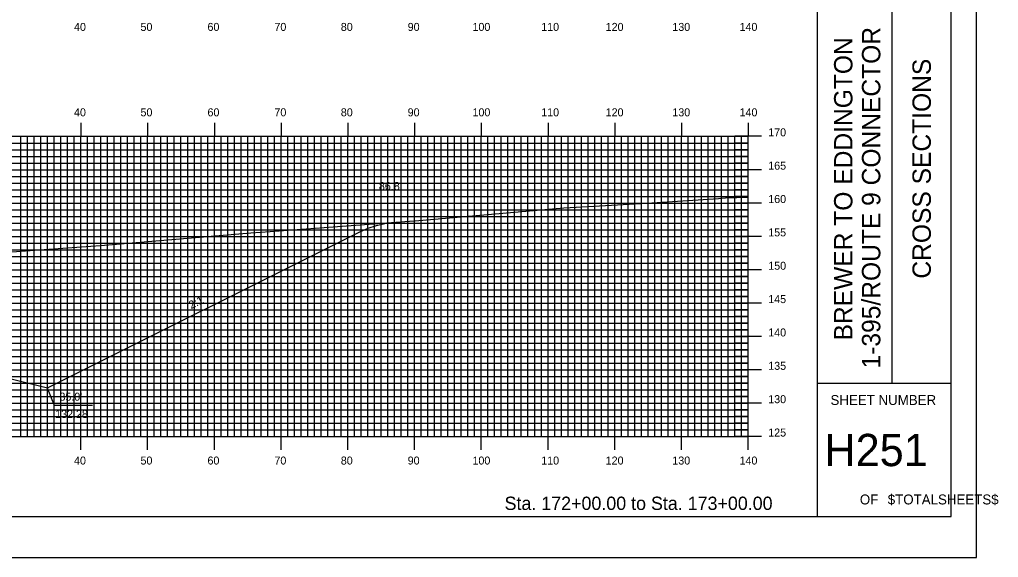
# Model space of a CAD drawing. Extents: x 1783041 to 1783384, y 442591 to 442811.
# Drawn here: x 1783237.3 to 1783384, y 442590.5 to 442671.2 of the extents above; entities that cross this region are included whole.
import ezdxf

# ---------------------------------------------------------------- set-up
doc = ezdxf.new("R2010")
doc.units = 0
for name, color, linetype in [('ANNOTATION', 7, 'Continuous'), ('BORDER', 7, 'Continuous'), ('D_Roadway_Centerline', 7, 'Continuous'), ('D_Roadway_SlopeLines', 7, 'Continuous'), ('D_Text_Standard', 7, 'Continuous'), ('H_V ANNOTATION', 7, 'Continuous'), ('MAJOR', 7, 'Continuous'), ('MINOR', 7, 'Continuous'), ('PLOT BOUNDARY', 7, 'Continuous'), ('S_Roadway_Centerline', 7, 'Continuous')]:
    doc.layers.add(name, color=color, linetype=linetype)

msp = doc.modelspace()

# ---------------------------------------------------------------- linework, layer by layer
at = {"layer": 'ANNOTATION'}
msp.add_lwpolyline([(1783248.2, 442613.32), (1783242.51, 442613.32), (1783241.4, 442616)], dxfattribs=at)
at = {"layer": 'BORDER'}
for p, q in [((1783356.86, 442596.67), (1783356.86, 442806.67)), ((1783368.04, 442616.67), (1783368.04, 442686.67)), ((1783368.04, 442616.67), (1783368.04, 442686.67)), ((1783356.86, 442616.67), (1783376.86, 442616.67)), ((1783356.86, 442616.67), (1783376.86, 442616.67))]:
    msp.add_line(p, q, dxfattribs=at)
msp.add_lwpolyline([(1783056.86, 442596.67), (1783376.86, 442596.67), (1783376.86, 442806.67), (1783056.86, 442806.67)], close=True, dxfattribs=at)
at = {"layer": 'D_Roadway_Centerline'}
msp.add_lwpolyline([(1783143.39, 442629.05), (1783144.64, 442629.1), (1783145.89, 442628.96), (1783147.14, 442628.63), (1783148.39, 442628.1), (1783172.29, 442616.15), (1783176.29, 442617.15), (1783186.46, 442619.69), (1783194.46, 442620.01), (1783206.46, 442620.25), (1783218.46, 442620.01), (1783226.46, 442619.69), (1783236.63, 442617.15), (1783241.45, 442615.95), (1783288.24, 442639.34), (1783289.49, 442639.9), (1783290.74, 442640.32), (1783291.99, 442640.61), (1783293.24, 442640.77)], dxfattribs=at)
at = {"layer": 'D_Roadway_SlopeLines'}
for points in [[(1783241.45, 442615.95), (1783288.24, 442639.34), (1783289.49, 442639.9), (1783290.74, 442640.32), (1783291.99, 442640.61), (1783293.24, 442640.77)], [(1783226.46, 442619.69), (1783241.45, 442615.95)]]:
    msp.add_lwpolyline(points, dxfattribs=at)
at = {"layer": 'MAJOR'}
for p, q in [((1783246.46, 442655.67), (1783246.46, 442653.67)), ((1783256.46, 442655.67), (1783256.46, 442653.67)), ((1783266.46, 442655.67), (1783266.46, 442653.67)), ((1783276.46, 442655.67), (1783276.46, 442653.67)), ((1783286.46, 442655.67), (1783286.46, 442653.67)), ((1783296.46, 442655.67), (1783296.46, 442653.67)), ((1783306.46, 442655.67), (1783306.46, 442653.67)), ((1783316.46, 442655.67), (1783316.46, 442653.67)), ((1783326.46, 442655.67), (1783326.46, 442653.67)), ((1783336.46, 442655.67), (1783336.46, 442653.67)), ((1783346.46, 442655.67), (1783346.46, 442653.67)), ((1783066.46, 442653.67), (1783346.46, 442653.67)), ((1783066.46, 442653.67), (1783346.46, 442653.67)), ((1783246.46, 442608.67), (1783246.46, 442653.67)), ((1783256.46, 442608.67), (1783256.46, 442653.67)), ((1783266.46, 442608.67), (1783266.46, 442653.67)), ((1783276.46, 442608.67), (1783276.46, 442653.67)), ((1783286.46, 442608.67), (1783286.46, 442653.67)), ((1783296.46, 442608.67), (1783296.46, 442653.67)), ((1783306.46, 442608.67), (1783306.46, 442653.67)), ((1783316.46, 442608.67), (1783316.46, 442653.67)), ((1783326.46, 442608.67), (1783326.46, 442653.67)), ((1783336.46, 442608.67), (1783336.46, 442653.67)), ((1783348.46, 442653.67), (1783344.46, 442653.67)), ((1783346.46, 442608.67), (1783346.46, 442653.67)), ((1783346.46, 442608.67), (1783346.46, 442653.67)), ((1783066.46, 442648.67), (1783346.46, 442648.67)), ((1783348.46, 442648.67), (1783344.46, 442648.67)), ((1783066.46, 442643.67), (1783346.46, 442643.67)), ((1783348.46, 442643.67), (1783344.46, 442643.67)), ((1783066.46, 442638.67), (1783346.46, 442638.67)), ((1783348.46, 442638.67), (1783344.46, 442638.67)), ((1783066.46, 442633.67), (1783346.46, 442633.67)), ((1783348.46, 442633.67), (1783344.46, 442633.67)), ((1783066.46, 442628.67), (1783346.46, 442628.67)), ((1783348.46, 442628.67), (1783344.46, 442628.67)), ((1783066.46, 442623.67), (1783346.46, 442623.67)), ((1783348.46, 442623.67), (1783344.46, 442623.67)), ((1783066.46, 442618.67), (1783346.46, 442618.67)), ((1783348.46, 442618.67), (1783344.46, 442618.67)), ((1783066.46, 442613.67), (1783346.46, 442613.67)), ((1783348.46, 442613.67), (1783344.46, 442613.67)), ((1783066.46, 442608.67), (1783346.46, 442608.67)), ((1783066.46, 442608.67), (1783346.46, 442608.67)), ((1783246.46, 442606.66), (1783246.46, 442608.67)), ((1783256.46, 442606.66), (1783256.46, 442608.67)), ((1783266.46, 442606.66), (1783266.46, 442608.67)), ((1783276.46, 442606.66), (1783276.46, 442608.67)), ((1783286.46, 442606.66), (1783286.46, 442608.67)), ((1783296.46, 442606.66), (1783296.46, 442608.67)), ((1783306.46, 442606.66), (1783306.46, 442608.67)), ((1783316.46, 442606.66), (1783316.46, 442608.67)), ((1783326.46, 442606.66), (1783326.46, 442608.67)), ((1783336.46, 442606.66), (1783336.46, 442608.67)), ((1783348.46, 442608.67), (1783344.46, 442608.67)), ((1783346.46, 442606.66), (1783346.46, 442608.67))]:
    msp.add_line(p, q, dxfattribs=at)
at = {"layer": 'MINOR'}
for p, q in [((1783066.46, 442652.67), (1783346.46, 442652.67)), ((1783237.46, 442608.67), (1783237.46, 442653.67)), ((1783238.46, 442608.67), (1783238.46, 442653.67)), ((1783239.46, 442608.67), (1783239.46, 442653.67)), ((1783240.46, 442608.67), (1783240.46, 442653.67)), ((1783241.46, 442608.67), (1783241.46, 442653.67)), ((1783242.46, 442608.67), (1783242.46, 442653.67)), ((1783243.46, 442608.67), (1783243.46, 442653.67)), ((1783244.46, 442608.67), (1783244.46, 442653.67)), ((1783245.46, 442608.67), (1783245.46, 442653.67)), ((1783247.46, 442608.67), (1783247.46, 442653.67)), ((1783248.46, 442608.67), (1783248.46, 442653.67)), ((1783249.46, 442608.67), (1783249.46, 442653.67)), ((1783250.46, 442608.67), (1783250.46, 442653.67)), ((1783251.46, 442608.67), (1783251.46, 442653.67)), ((1783252.46, 442608.67), (1783252.46, 442653.67)), ((1783253.46, 442608.67), (1783253.46, 442653.67)), ((1783254.46, 442608.67), (1783254.46, 442653.67)), ((1783255.46, 442608.67), (1783255.46, 442653.67)), ((1783257.46, 442608.67), (1783257.46, 442653.67)), ((1783258.46, 442608.67), (1783258.46, 442653.67)), ((1783259.46, 442608.67), (1783259.46, 442653.67)), ((1783260.46, 442608.67), (1783260.46, 442653.67)), ((1783261.46, 442608.67), (1783261.46, 442653.67)), ((1783262.46, 442608.67), (1783262.46, 442653.67)), ((1783263.46, 442608.67), (1783263.46, 442653.67)), ((1783264.46, 442608.67), (1783264.46, 442653.67)), ((1783265.46, 442608.67), (1783265.46, 442653.67)), ((1783267.46, 442608.67), (1783267.46, 442653.67)), ((1783268.46, 442608.67), (1783268.46, 442653.67)), ((1783269.46, 442608.67), (1783269.46, 442653.67)), ((1783270.46, 442608.67), (1783270.46, 442653.67)), ((1783271.46, 442608.67), (1783271.46, 442653.67)), ((1783272.46, 442608.67), (1783272.46, 442653.67)), ((1783273.46, 442608.67), (1783273.46, 442653.67)), ((1783274.46, 442608.67), (1783274.46, 442653.67)), ((1783275.46, 442608.67), (1783275.46, 442653.67)), ((1783277.46, 442608.67), (1783277.46, 442653.67)), ((1783278.46, 442608.67), (1783278.46, 442653.67)), ((1783279.46, 442608.67), (1783279.46, 442653.67)), ((1783280.46, 442608.67), (1783280.46, 442653.67)), ((1783281.46, 442608.67), (1783281.46, 442653.67)), ((1783282.46, 442608.67), (1783282.46, 442653.67)), ((1783283.46, 442608.67), (1783283.46, 442653.67)), ((1783284.46, 442608.67), (1783284.46, 442653.67)), ((1783285.46, 442608.67), (1783285.46, 442653.67)), ((1783287.46, 442608.67), (1783287.46, 442653.67)), ((1783288.46, 442608.67), (1783288.46, 442653.67)), ((1783289.46, 442608.67), (1783289.46, 442653.67)), ((1783290.46, 442608.67), (1783290.46, 442653.67)), ((1783291.46, 442608.67), (1783291.46, 442653.67)), ((1783292.46, 442608.67), (1783292.46, 442653.67)), ((1783293.46, 442608.67), (1783293.46, 442653.67)), ((1783294.46, 442608.67), (1783294.46, 442653.67)), ((1783295.46, 442608.67), (1783295.46, 442653.67)), ((1783297.46, 442608.67), (1783297.46, 442653.67)), ((1783298.46, 442608.67), (1783298.46, 442653.67)), ((1783299.46, 442608.67), (1783299.46, 442653.67)), ((1783300.46, 442608.67), (1783300.46, 442653.67)), ((1783301.46, 442608.67), (1783301.46, 442653.67)), ((1783302.46, 442608.67), (1783302.46, 442653.67)), ((1783303.46, 442608.67), (1783303.46, 442653.67)), ((1783304.46, 442608.67), (1783304.46, 442653.67)), ((1783305.46, 442608.67), (1783305.46, 442653.67)), ((1783307.46, 442608.67), (1783307.46, 442653.67)), ((1783308.46, 442608.67), (1783308.46, 442653.67)), ((1783309.46, 442608.67), (1783309.46, 442653.67)), ((1783310.46, 442608.67), (1783310.46, 442653.67)), ((1783311.46, 442608.67), (1783311.46, 442653.67)), ((1783312.46, 442608.67), (1783312.46, 442653.67)), ((1783313.46, 442608.67), (1783313.46, 442653.67)), ((1783314.46, 442608.67), (1783314.46, 442653.67)), ((1783315.46, 442608.67), (1783315.46, 442653.67)), ((1783317.46, 442608.67), (1783317.46, 442653.67)), ((1783318.46, 442608.67), (1783318.46, 442653.67)), ((1783319.46, 442608.67), (1783319.46, 442653.67)), ((1783320.46, 442608.67), (1783320.46, 442653.67)), ((1783321.46, 442608.67), (1783321.46, 442653.67)), ((1783322.46, 442608.67), (1783322.46, 442653.67)), ((1783323.46, 442608.67), (1783323.46, 442653.67)), ((1783324.46, 442608.67), (1783324.46, 442653.67)), ((1783325.46, 442608.67), (1783325.46, 442653.67)), ((1783327.46, 442608.67), (1783327.46, 442653.67)), ((1783328.46, 442608.67), (1783328.46, 442653.67)), ((1783329.46, 442608.67), (1783329.46, 442653.67)), ((1783330.46, 442608.67), (1783330.46, 442653.67)), ((1783331.46, 442608.67), (1783331.46, 442653.67)), ((1783332.46, 442608.67), (1783332.46, 442653.67)), ((1783333.46, 442608.67), (1783333.46, 442653.67)), ((1783334.46, 442608.67), (1783334.46, 442653.67)), ((1783335.46, 442608.67), (1783335.46, 442653.67)), ((1783337.46, 442608.67), (1783337.46, 442653.67)), ((1783338.46, 442608.67), (1783338.46, 442653.67)), ((1783339.46, 442608.67), (1783339.46, 442653.67)), ((1783340.46, 442608.67), (1783340.46, 442653.67)), ((1783341.46, 442608.67), (1783341.46, 442653.67)), ((1783342.46, 442608.67), (1783342.46, 442653.67)), ((1783343.46, 442608.67), (1783343.46, 442653.67)), ((1783344.46, 442608.67), (1783344.46, 442653.67)), ((1783346.46, 442652.67), (1783344.46, 442652.67)), ((1783345.46, 442608.67), (1783345.46, 442653.67)), ((1783066.46, 442651.67), (1783346.46, 442651.67)), ((1783346.46, 442651.67), (1783344.46, 442651.67)), ((1783066.46, 442650.67), (1783346.46, 442650.67)), ((1783066.46, 442649.67), (1783346.46, 442649.67)), ((1783346.46, 442650.67), (1783344.46, 442650.67)), ((1783346.46, 442649.67), (1783344.46, 442649.67)), ((1783066.46, 442647.67), (1783346.46, 442647.67)), ((1783066.46, 442646.67), (1783346.46, 442646.67)), ((1783346.46, 442647.67), (1783344.46, 442647.67)), ((1783346.46, 442646.67), (1783344.46, 442646.67)), ((1783066.46, 442645.67), (1783346.46, 442645.67)), ((1783346.46, 442645.67), (1783344.46, 442645.67)), ((1783066.46, 442644.67), (1783346.46, 442644.67)), ((1783346.46, 442644.67), (1783344.46, 442644.67)), ((1783066.46, 442642.67), (1783346.46, 442642.67)), ((1783346.46, 442642.67), (1783344.46, 442642.67)), ((1783066.46, 442641.67), (1783346.46, 442641.67)), ((1783066.46, 442640.67), (1783346.46, 442640.67)), ((1783346.46, 442641.67), (1783344.46, 442641.67)), ((1783346.46, 442640.67), (1783344.46, 442640.67)), ((1783066.46, 442639.67), (1783346.46, 442639.67)), ((1783346.46, 442639.67), (1783344.46, 442639.67)), ((1783066.46, 442637.67), (1783346.46, 442637.67)), ((1783346.46, 442637.67), (1783344.46, 442637.67)), ((1783066.46, 442636.67), (1783346.46, 442636.67)), ((1783346.46, 442636.67), (1783344.46, 442636.67)), ((1783066.46, 442635.67), (1783346.46, 442635.67)), ((1783346.46, 442635.67), (1783344.46, 442635.67)), ((1783066.46, 442634.67), (1783346.46, 442634.67)), ((1783346.46, 442634.67), (1783344.46, 442634.67)), ((1783066.46, 442632.67), (1783346.46, 442632.67)), ((1783346.46, 442632.67), (1783344.46, 442632.67)), ((1783066.46, 442631.67), (1783346.46, 442631.67)), ((1783066.46, 442630.67), (1783346.46, 442630.67)), ((1783346.46, 442631.67), (1783344.46, 442631.67)), ((1783346.46, 442630.67), (1783344.46, 442630.67)), ((1783066.46, 442629.67), (1783346.46, 442629.67)), ((1783346.46, 442629.67), (1783344.46, 442629.67)), ((1783066.46, 442627.67), (1783346.46, 442627.67)), ((1783346.46, 442627.67), (1783344.46, 442627.67)), ((1783066.46, 442626.67), (1783346.46, 442626.67)), ((1783346.46, 442626.67), (1783344.46, 442626.67)), ((1783066.46, 442625.67), (1783346.46, 442625.67)), ((1783066.46, 442624.67), (1783346.46, 442624.67)), ((1783346.46, 442625.67), (1783344.46, 442625.67)), ((1783346.46, 442624.67), (1783344.46, 442624.67)), ((1783066.46, 442622.67), (1783346.46, 442622.67)), ((1783066.46, 442621.67), (1783346.46, 442621.67)), ((1783346.46, 442622.67), (1783344.46, 442622.67)), ((1783346.46, 442621.67), (1783344.46, 442621.67)), ((1783066.46, 442620.67), (1783346.46, 442620.67)), ((1783346.46, 442620.67), (1783344.46, 442620.67)), ((1783066.46, 442619.67), (1783346.46, 442619.67)), ((1783346.46, 442619.67), (1783344.46, 442619.67)), ((1783066.46, 442617.67), (1783346.46, 442617.67)), ((1783346.46, 442617.67), (1783344.46, 442617.67)), ((1783066.46, 442616.67), (1783346.46, 442616.67)), ((1783066.46, 442615.67), (1783346.46, 442615.67)), ((1783346.46, 442616.67), (1783344.46, 442616.67)), ((1783346.46, 442615.67), (1783344.46, 442615.67)), ((1783066.46, 442614.67), (1783346.46, 442614.67)), ((1783346.46, 442614.67), (1783344.46, 442614.67)), ((1783066.46, 442612.67), (1783346.46, 442612.67)), ((1783066.46, 442611.67), (1783346.46, 442611.67)), ((1783346.46, 442612.67), (1783344.46, 442612.67)), ((1783346.46, 442611.67), (1783344.46, 442611.67)), ((1783066.46, 442610.67), (1783346.46, 442610.67)), ((1783346.46, 442610.67), (1783344.46, 442610.67)), ((1783066.46, 442609.67), (1783346.46, 442609.67)), ((1783346.46, 442609.67), (1783344.46, 442609.67))]:
    msp.add_line(p, q, dxfattribs=at)
at = {"layer": 'PLOT BOUNDARY'}
msp.add_lwpolyline([(1783040.67, 442590.55), (1783380.67, 442590.55), (1783380.67, 442810.55), (1783040.67, 442810.55)], close=True, dxfattribs=at)
at = {"layer": 'S_Roadway_Centerline'}
msp.add_lwpolyline([(1783226.96, 442635.7), (1783247.96, 442637.22), (1783249.39, 442637.29), (1783250.58, 442637.41), (1783271.92, 442639.18), (1783274.82, 442639.38), (1783284.27, 442640.12), (1783296.37, 442641), (1783296.45, 442641), (1783296.53, 442641.01), (1783318.83, 442642.94), (1783319.76, 442643), (1783331.27, 442643.66), (1783342.02, 442644.37), (1783343.07, 442644.43), (1783346.46, 442644.54)], dxfattribs=at)

# ---------------------------------------------------------------- texts
at = {"layer": 'ANNOTATION'}
msp.add_text('2:1', height=1.2, rotation=26.5651, dxfattribs=at).set_placement((1783262.99, 442627.75))
for s, p in [("35.0'", (1783243.24, 442614.04)), ('132.28', (1783242.6, 442611.44))]:
    msp.add_text(s, height=1.2, dxfattribs=at).set_placement(p)
at = {"layer": 'BORDER'}
for s, p in [('1-395/ROUTE 9 CONNECTOR', (1783366.26, 442618.87)), ('BREWER TO EDDINGTON', (1783362.08, 442623.07)), ('CROSS SECTIONS', (1783373.83, 442632.34)), ('CROSS SECTIONS', (1783373.83, 442632.34))]:
    msp.add_text(s, height=2.7557, rotation=90, dxfattribs=at).set_placement(p)
for s, height, p in [('SHEET NUMBER', 1.4905, (1783358.79, 442613.4)), ('SHEET NUMBER', 1.4905, (1783358.79, 442613.4)), ('H251', 4.839, (1783357.89, 442604.23)), ('OF', 1.491, (1783363.19, 442598.49)), ('OF', 1.491, (1783363.19, 442598.49)), ('$TOTALSHEETS$', 1.4905, (1783367.37, 442598.49)), ('$TOTALSHEETS$', 1.4905, (1783367.37, 442598.49))]:
    msp.add_text(s, height=height, dxfattribs=at).set_placement(p)
at = {"layer": 'D_Text_Standard'}
msp.add_text("86.8'", height=1.2, dxfattribs=at).set_placement((1783291.12, 442645.61))
at = {"layer": 'H_V ANNOTATION'}
for s, height, p in [('40', 1.2, (1783245.43, 442669.47)), ('50', 1.2, (1783255.39, 442669.47)), ('60', 1.2, (1783265.43, 442669.47)), ('70', 1.2, (1783275.46, 442669.47)), ('80', 1.2, (1783285.41, 442669.47)), ('90', 1.2, (1783295.43, 442669.47)), ('100', 1.2, (1783305.14, 442669.47)), ('110', 1.2, (1783315.44, 442669.47)), ('120', 1.2, (1783325.1, 442669.47)), ('130', 1.2, (1783335.09, 442669.47)), ('140', 1.2, (1783345.16, 442669.47)), ('40', 1.2, (1783245.43, 442656.67)), ('50', 1.2, (1783255.39, 442656.67)), ('60', 1.2, (1783265.43, 442656.67)), ('70', 1.2, (1783275.46, 442656.67)), ('80', 1.2, (1783285.41, 442656.67)), ('90', 1.2, (1783295.43, 442656.67)), ('100', 1.2, (1783305.14, 442656.67)), ('110', 1.2, (1783315.44, 442656.67)), ('120', 1.2, (1783325.1, 442656.67)), ('130', 1.2, (1783335.09, 442656.67)), ('140', 1.2, (1783345.16, 442656.67)), ('170', 1.2, (1783349.46, 442653.67)), ('165', 1.2, (1783349.46, 442648.67)), ('160', 1.2, (1783349.46, 442643.67)), ('155', 1.2, (1783349.46, 442638.67)), ('150', 1.2, (1783349.46, 442633.67)), ('145', 1.2, (1783349.46, 442628.67)), ('140', 1.2, (1783349.46, 442623.67)), ('135', 1.2, (1783349.46, 442618.67)), ('130', 1.2, (1783349.46, 442613.67)), ('125', 1.2, (1783349.46, 442608.67)), ('40', 1.2, (1783245.43, 442604.47)), ('50', 1.2, (1783255.39, 442604.47)), ('60', 1.2, (1783265.43, 442604.47)), ('70', 1.2, (1783275.46, 442604.47)), ('80', 1.2, (1783285.41, 442604.47)), ('90', 1.2, (1783295.43, 442604.47)), ('100', 1.2, (1783305.14, 442604.47)), ('110', 1.2, (1783315.44, 442604.47)), ('120', 1.2, (1783325.1, 442604.47)), ('130', 1.2, (1783335.09, 442604.47)), ('140', 1.2, (1783345.16, 442604.47)), ('Sta. 172+00.00 to Sta. 173+00.00', 2.0004, (1783309.95, 442597.66))]:
    msp.add_text(s, height=height, dxfattribs=at).set_placement(p)

doc.saveas('drawing.dxf')
